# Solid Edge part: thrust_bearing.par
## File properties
Title: Solid Edge 20
Author: vicky raina
Template: Normal.par
Last saved by: Robert a Rhodes jr
Revision: 8
Application: Solid Edge
Material: aluminum
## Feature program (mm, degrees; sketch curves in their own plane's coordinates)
sketch for "unnamed RevolvedProtrusion 1" plane through (0, 0, 0) normal (0, -1, 0) x-axis (1, 0, 0)
  line (47.625, 16.8036) -> (66.929, 16.8036)
  line (66.929, 16.8036) -> (73.025, 10.7076)
  line (73.025, 10.7076) -> (73.025, -12.0254)
  line (73.025, -12.0254) -> (66.929, -18.1214)
  line (66.929, -18.1214) -> (47.625, -18.1214)
  line (47.625, -18.1214) -> (47.625, -7.1994)
  line (61.5714, -7.1994) -> (47.625, -7.1994)
  line (61.5714, 5.8816) -> (61.5714, -7.1994)
  line (47.625, 5.8816) -> (61.5714, 5.8816)
  line (47.625, 5.8816) -> (47.625, 16.8036)
revolve "unnamed RevolvedProtrusion 1" add finite 360 deg
sketch for "unnamed RevolvedProtrusion 2" plane through (0, 0, 0) normal (1, 0, 0) x-axis (0, 1, 0)
  line (69.977, 13.7556) -> (73.0652, 13.7556)
  line (73.0652, 13.7556) -> (74.6125, 12.2083)
  line (74.6125, 12.2083) -> (74.6125, -13.4669)
  line (74.6125, -13.4669) -> (73.006, -15.0734)
  line (73.006, -15.0734) -> (69.977, -15.0734)
revolve "unnamed RevolvedProtrusion 2" add full turn 360 deg
sketch for "unnamed RevolvedProtrusion 3" plane through (0, 0, 0) normal (0, -1, 0) x-axis (1, 0, 0)
revolve "unnamed RevolvedProtrusion 3" add full turn 360 deg about sketch line (-54.9674, 10.1232) -> (-54.9674, -18.1214)
pattern "unnamed Pattern 1" of "unnamed RevolvedProtrusion 3"
pattern "unnamed Pattern 2"
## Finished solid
Body 1: solid body, 39 faces, 39 edges, 25 vertices.
  Faces by surface: torus 25, plane 6, cone 4, cylinder 4
  Edges by curve: circle 39
Bounding box of the edges (mm; curved faces can reach further): 149.225 x 149.225 x 34.925, from (-74.6125, -74.6125, -18.1214) to (74.6125, 74.6125, 16.8036).
Cylindrical faces by radius (mm): R47.625 x2, R61.5714 x1, R74.6125 x1
Conical faces (half-angle, radius in mm at the cone's reference point): 45 deg R66.929 x1, 45 deg R73.025 x1, 45 deg R73.0652 x1, 45 deg R74.6125 x1
Toroidal faces (ring radius, tube radius in mm): R-0.1023 r6.604 x25
Planar faces by outward normal: +z 3, -z 3
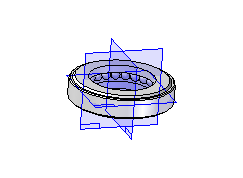
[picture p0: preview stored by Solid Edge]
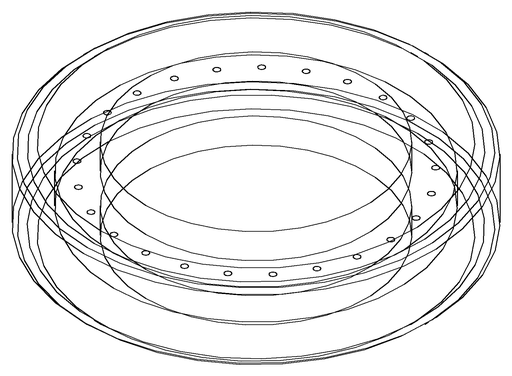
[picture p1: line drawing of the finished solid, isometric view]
